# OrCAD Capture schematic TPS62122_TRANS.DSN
size D
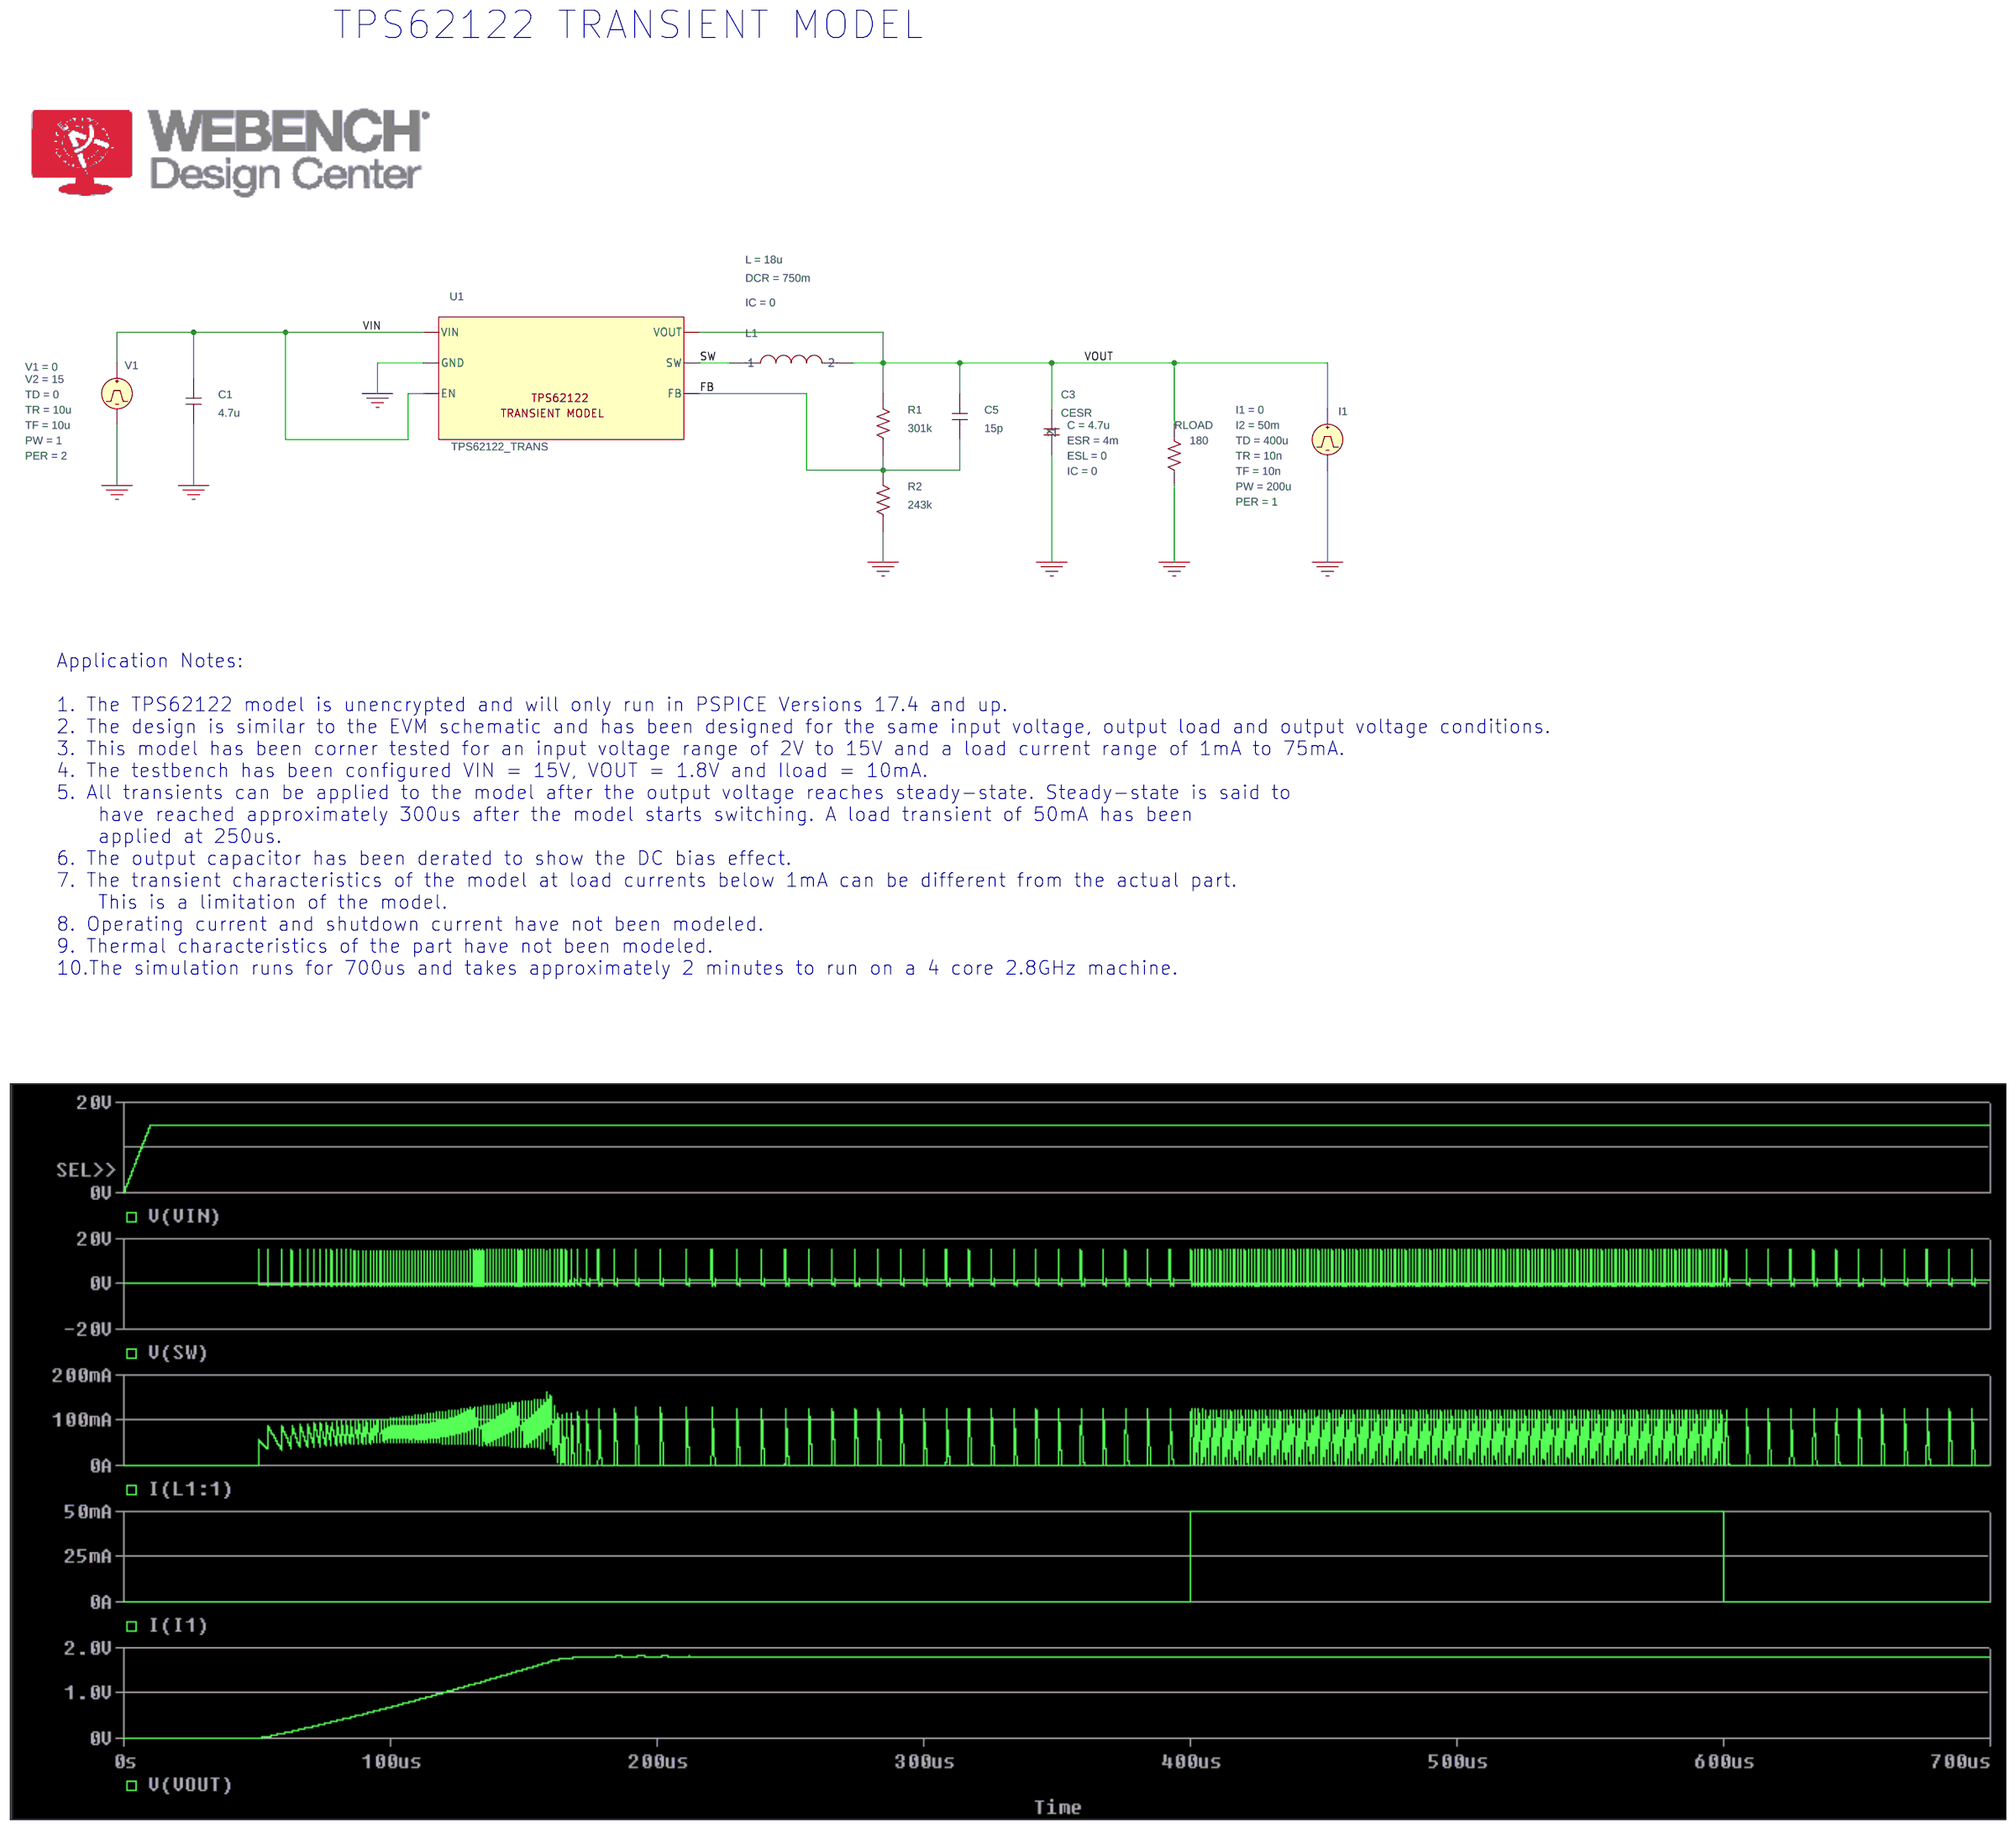
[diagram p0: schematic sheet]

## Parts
C1  4.7u  [RAD/CK05]
C3  CESR
C5  15p  [RAD/CK05]
I1  IPULSE
L1  LDCR
R1  301k  [AX/RC05]
R2  243k  [AX/RC05]
RLOAD  180  [AX/RC05]
U1  TPS62122_TRANS
V1  VPULSE

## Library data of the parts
C1 C5 = C
C3 = CESR: C: 4.7u; ESL: 0; ESR: 4m; IC: 0; PSpiceTemplate: X^@REFDES %1 %2 @MODEL PARAMS: ?C|C=@C||C=10U| ?ESR|ESR=@ESR||ESR=2M| ?ESL|ESL=@ESL||ESL=1N| ?IC|IC=@IC||IC=0|
I1 = IPULSE: I1: 0; I2: 50m; PER: 1; PW: 200u; TD: 400u; TF: 10n; TR: 10n
L1 = LDCR: DCR: 750m; IC: 0; L: 18u
R1 R2 RLOAD = R
U1 = TPS62122_TRANS
V1 = VPULSE: PER: 2; PW: 1; TD: 0; TF: 10u; TR: 10u; V1: 0; V2: 15

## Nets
VIN: C1.2 U1.EN U1.VIN V1.1(+)
0: C1.1 C3.2 I1.2(-) R2.1 RLOAD.2 U1.GND V1.2(-)
FB: C5.1 R1.1 R2.2 U1.FB
SW: L1.1 U1.SW
VOUT: C3.1 C5.2 I1.1(+) L1.2 R1.2 RLOAD.1 U1.VOUT

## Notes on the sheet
- TPS62122 TRANSIENT MODEL
- Application Notes:
  1. The TPS62122 model is unencrypted and will only run in PSPICE Versions 17.4 and up.
  2. The design is similar to the EVM schematic and has been designed for the same input voltage, output load and output voltage conditions.
  3. This model has been corner tested for an input voltage range of 2V to 15V and a load current range of 1mA to 75mA.
  4. The testbench has been configured VIN = 15V, VOUT = 1.8V and Iload = 10mA.
  5. All transients can be applied to the model after the output voltage reaches steady-state. Steady-state is said to
      have reached approximately 300us after the model starts switching. A load transient of 50mA has been
      applied at 250us.
  6. The output capacitor has been derated to show the DC bias effect.
  7. The transient characteristics of the model at load currents below 1mA can be different from the actual part.
      This is a limitation of the model.
  8. Operating current and shutdown current have not been modeled.
  9. Thermal characteristics of the part have not been modeled.
  10.The simulation runs for 700us and takes approximately 2 minutes to run on a 4 core 2.8GHz machine.
